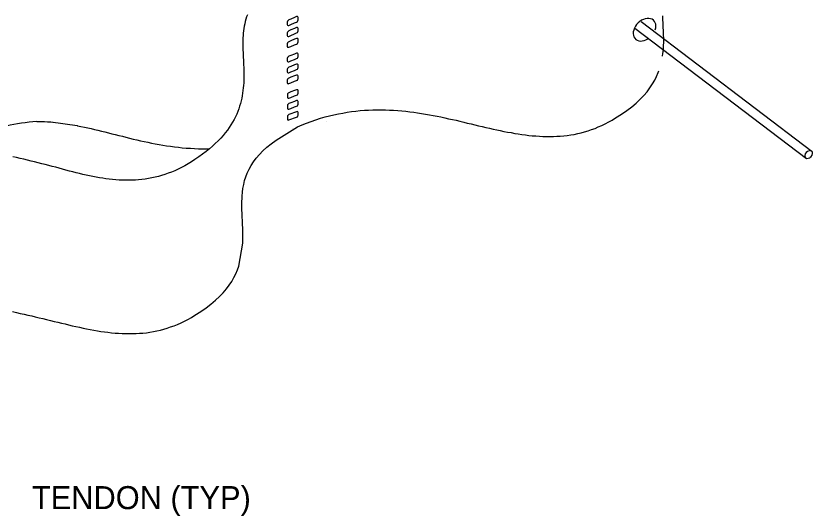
# Model space of a CAD drawing. Extents: x 638850 to 644908, y 297188 to 298900.
# Drawn here: x 639299.1 to 639402.9, y 297714.3 to 297779.5 of the extents above; entities that cross this region are included whole.
import ezdxf

# ---------------------------------------------------------------- set-up
doc = ezdxf.new("R2010")
doc.units = 0
for name, color, linetype in [('1', 7, 'Continuous'), ('16', 7, 'Continuous'), ('2', 7, 'Continuous')]:
    doc.layers.add(name, color=color, linetype=linetype)

msp = doc.modelspace()

# ---------------------------------------------------------------- linework, layer by layer
at = {"layer": '1'}
for p, q in [((639379.74, 297777.89), (639402.11, 297760.88)), ((639380.55, 297778.76), (639402.82, 297761.82))]:
    msp.add_line(p, q, dxfattribs=at)
msp.add_arc((639304.02, 297736.88), 28.92, 94.4334, 102.4037, dxfattribs=at)
for centre, major_axis, start_param in [((639380.98, 297777.69), (-1.2, -1.2), 2.18443), ((639402.37, 297761.42), (-0.416, -0.414), 1.264481)]:
    msp.add_ellipse(centre, major_axis=major_axis, ratio=0.717222, start_param=start_param, end_param=7.533439, dxfattribs=at)
at = {"layer": '16'}
for points in [[(639335.65, 297778.69), (639335.75, 297778.75), (639335.82, 297778.85), (639335.86, 297778.96), (639335.86, 297778.96), (639335.86, 297779.05), (639335.86, 297779.2), (639335.86, 297779.29), (639335.86, 297779.29), (639335.82, 297779.37), (639335.75, 297779.42), (639335.65, 297779.4), (639335.65, 297779.4), (639335.39, 297779.29), (639334.88, 297779.08), (639334.62, 297778.97), (639334.62, 297778.97), (639334.53, 297778.9), (639334.45, 297778.8), (639334.42, 297778.69), (639334.42, 297778.69), (639334.42, 297778.62), (639334.42, 297778.45), (639334.42, 297778.37), (639334.42, 297778.37), (639334.45, 297778.28), (639334.53, 297778.24), (639334.62, 297778.24), (639334.62, 297778.24), (639334.88, 297778.37), (639335.39, 297778.57), (639335.65, 297778.69), (639335.65, 297778.69), (639335.65, 297778.69)], [(639335.65, 297777.26), (639335.75, 297777.32), (639335.82, 297777.41), (639335.86, 297777.52), (639335.86, 297777.52), (639335.86, 297777.61), (639335.86, 297777.77), (639335.86, 297777.86), (639335.86, 297777.86), (639335.82, 297777.95), (639335.75, 297777.98), (639335.65, 297777.97), (639335.65, 297777.97), (639335.39, 297777.86), (639334.88, 297777.66), (639334.62, 297777.53), (639334.62, 297777.53), (639334.53, 297777.47), (639334.45, 297777.38), (639334.42, 297777.27), (639334.42, 297777.27), (639334.42, 297777.19), (639334.42, 297777.03), (639334.42, 297776.95), (639334.42, 297776.95), (639334.45, 297776.86), (639334.53, 297776.81), (639334.62, 297776.82), (639334.62, 297776.82), (639334.88, 297776.95), (639335.39, 297777.15), (639335.65, 297777.26), (639335.65, 297777.26), (639335.65, 297777.26)], [(639335.65, 297775.82), (639335.75, 297775.9), (639335.82, 297775.99), (639335.86, 297776.1), (639335.86, 297776.1), (639335.86, 297776.18), (639335.86, 297776.35), (639335.86, 297776.42), (639335.86, 297776.42), (639335.82, 297776.52), (639335.75, 297776.55), (639335.65, 297776.55), (639335.65, 297776.55), (639335.39, 297776.44), (639334.88, 297776.22), (639334.62, 297776.11), (639334.62, 297776.11), (639334.53, 297776.05), (639334.45, 297775.96), (639334.42, 297775.85), (639334.42, 297775.85), (639334.42, 297775.76), (639334.42, 297775.6), (639334.42, 297775.53), (639334.42, 297775.53), (639334.45, 297775.43), (639334.53, 297775.39), (639334.62, 297775.4), (639334.62, 297775.4), (639334.88, 297775.51), (639335.39, 297775.71), (639335.65, 297775.82), (639335.65, 297775.82), (639335.65, 297775.82)], [(639335.65, 297773.92), (639335.75, 297773.98), (639335.82, 297774.08), (639335.86, 297774.18), (639335.86, 297774.18), (639335.86, 297774.26), (639335.86, 297774.43), (639335.86, 297774.51), (639335.86, 297774.51), (639335.82, 297774.6), (639335.75, 297774.65), (639335.65, 297774.63), (639335.65, 297774.63), (639335.39, 297774.52), (639334.88, 297774.32), (639334.62, 297774.22), (639334.62, 297774.22), (639334.53, 297774.15), (639334.45, 297774.06), (639334.42, 297773.95), (639334.42, 297773.95), (639334.42, 297773.88), (639334.42, 297773.71), (639334.42, 297773.63), (639334.42, 297773.63), (639334.45, 297773.54), (639334.53, 297773.49), (639334.62, 297773.5), (639334.62, 297773.5), (639334.88, 297773.61), (639335.39, 297773.81), (639335.65, 297773.92), (639335.65, 297773.92), (639335.65, 297773.92)], [(639335.65, 297772.49), (639335.75, 297772.55), (639335.82, 297772.64), (639335.86, 297772.75), (639335.86, 297772.75), (639335.86, 297772.84), (639335.86, 297773), (639335.86, 297773.09), (639335.86, 297773.09), (639335.82, 297773.17), (639335.75, 297773.21), (639335.65, 297773.2), (639335.65, 297773.2), (639335.39, 297773.1), (639334.88, 297772.9), (639334.62, 297772.79), (639334.62, 297772.79), (639334.53, 297772.73), (639334.45, 297772.64), (639334.42, 297772.53), (639334.42, 297772.53), (639334.42, 297772.45), (639334.42, 297772.29), (639334.42, 297772.21), (639334.42, 297772.21), (639334.45, 297772.12), (639334.53, 297772.07), (639334.62, 297772.08), (639334.62, 297772.08), (639334.88, 297772.19), (639335.39, 297772.38), (639335.65, 297772.49), (639335.65, 297772.49), (639335.65, 297772.49)], [(639335.65, 297771.05), (639335.75, 297771.11), (639335.82, 297771.22), (639335.86, 297771.31), (639335.86, 297771.31), (639335.86, 297771.41), (639335.86, 297771.56), (639335.86, 297771.65), (639335.86, 297771.65), (639335.82, 297771.74), (639335.75, 297771.78), (639335.65, 297771.78), (639335.65, 297771.78), (639335.39, 297771.67), (639334.88, 297771.48), (639334.62, 297771.37), (639334.62, 297771.37), (639334.53, 297771.31), (639334.45, 297771.22), (639334.42, 297771.11), (639334.42, 297771.11), (639334.42, 297771.02), (639334.42, 297770.86), (639334.42, 297770.79), (639334.42, 297770.79), (639334.45, 297770.69), (639334.53, 297770.65), (639334.62, 297770.66), (639334.62, 297770.66), (639334.88, 297770.77), (639335.39, 297770.96), (639335.65, 297771.05), (639335.65, 297771.05), (639335.65, 297771.05)], [(639335.65, 297769.15), (639335.76, 297769.21), (639335.82, 297769.3), (639335.86, 297769.41), (639335.86, 297769.41), (639335.86, 297769.5), (639335.86, 297769.66), (639335.86, 297769.75), (639335.86, 297769.75), (639335.82, 297769.83), (639335.76, 297769.87), (639335.65, 297769.86), (639335.65, 297769.86), (639335.39, 297769.77), (639334.88, 297769.58), (639334.62, 297769.47), (639334.62, 297769.47), (639334.53, 297769.41), (639334.45, 297769.32), (639334.44, 297769.21), (639334.44, 297769.21), (639334.44, 297769.13), (639334.44, 297768.96), (639334.44, 297768.89), (639334.44, 297768.89), (639334.45, 297768.79), (639334.53, 297768.76), (639334.62, 297768.76), (639334.62, 297768.76), (639334.88, 297768.87), (639335.39, 297769.06), (639335.65, 297769.15), (639335.65, 297769.15), (639335.65, 297769.15)], [(639335.65, 297767.71), (639335.76, 297767.77), (639335.82, 297767.87), (639335.86, 297767.98), (639335.86, 297767.98), (639335.86, 297768.07), (639335.86, 297768.22), (639335.86, 297768.32), (639335.86, 297768.32), (639335.82, 297768.39), (639335.76, 297768.44), (639335.65, 297768.44), (639335.65, 297768.44), (639335.39, 297768.33), (639334.88, 297768.15), (639334.62, 297768.05), (639334.62, 297768.05), (639334.53, 297767.99), (639334.45, 297767.9), (639334.44, 297767.79), (639334.44, 297767.79), (639334.44, 297767.71), (639334.44, 297767.54), (639334.44, 297767.47), (639334.44, 297767.47), (639334.45, 297767.37), (639334.53, 297767.33), (639334.62, 297767.34), (639334.62, 297767.34), (639334.88, 297767.43), (639335.39, 297767.62), (639335.65, 297767.71), (639335.65, 297767.71), (639335.65, 297767.71)], [(639335.65, 297766.29), (639335.76, 297766.35), (639335.82, 297766.45), (639335.86, 297766.54), (639335.86, 297766.54), (639335.86, 297766.63), (639335.86, 297766.8), (639335.86, 297766.88), (639335.86, 297766.88), (639335.82, 297766.97), (639335.76, 297767.02), (639335.65, 297767), (639335.65, 297767), (639335.39, 297766.91), (639334.88, 297766.72), (639334.62, 297766.63), (639334.62, 297766.63), (639334.53, 297766.57), (639334.45, 297766.48), (639334.44, 297766.37), (639334.44, 297766.37), (639334.44, 297766.29), (639334.44, 297766.12), (639334.44, 297766.05), (639334.44, 297766.05), (639334.45, 297765.95), (639334.53, 297765.91), (639334.62, 297765.92), (639334.62, 297765.92), (639334.88, 297766.01), (639335.39, 297766.2), (639335.65, 297766.29), (639335.65, 297766.29), (639335.65, 297766.29)]]:
    msp.add_lwpolyline(points, dxfattribs=at)
at = {"layer": '2'}
for p, q in [((639339.35, 297766.31), (639339.94, 297766.46)), ((639339.94, 297766.46), (639340.5, 297766.6)), ((639340.5, 297766.6), (639341.09, 297766.72)), ((639341.09, 297766.72), (639341.67, 297766.83)), ((639341.67, 297766.83), (639342.23, 297766.93)), ((639342.23, 297766.93), (639342.79, 297767.02)), ((639342.79, 297767.02), (639343.36, 297767.08)), ((639343.36, 297767.08), (639343.92, 297767.14)), ((639343.92, 297767.14), (639344.48, 297767.19)), ((639344.48, 297767.19), (639345.03, 297767.22)), ((639345.03, 297767.22), (639345.59, 297767.24)), ((639345.59, 297767.24), (639346.13, 297767.25)), ((639346.13, 297767.25), (639346.67, 297767.25)), ((639346.67, 297767.25), (639347.21, 297767.24)), ((639347.21, 297767.24), (639347.75, 297767.22)), ((639347.75, 297767.22), (639348.27, 297767.19)), ((639348.27, 297767.19), (639348.82, 297767.16)), ((639348.82, 297767.16), (639349.34, 297767.11)), ((639349.34, 297767.11), (639349.86, 297767.05)), ((639303.63, 297765.66), (639307.04, 297765.19)), ((639336.35, 297765.29), (639336.95, 297765.52)), ((639336.95, 297765.52), (639337.56, 297765.74)), ((639337.56, 297765.74), (639338.16, 297765.95)), ((639338.16, 297765.95), (639338.76, 297766.14)), ((639338.76, 297766.14), (639339.35, 297766.31)), ((639339.59, 297765.71), (639339.59, 297765.71)), ((639333.67, 297763.71), (639335.75, 297765.03)), ((639335.13, 297764.75), (639335.13, 297764.75)), ((639335.75, 297765.03), (639336.35, 297765.29)), ((639332.98, 297763.27), (639333.67, 297763.71)), ((639331.26, 297761.89), (639331.77, 297762.36)), ((639331.77, 297762.36), (639332.34, 297762.82)), ((639332.34, 297762.82), (639332.98, 297763.27)), ((639330.38, 297760.94), (639330.8, 297761.41)), ((639330.8, 297761.41), (639331.26, 297761.89)), ((639329.72, 297759.99), (639330.03, 297760.46)), ((639330.03, 297760.46), (639330.38, 297760.94)), ((639329.21, 297759.01), (639329.44, 297759.5)), ((639329.44, 297759.5), (639329.72, 297759.99)), ((639328.87, 297758.02), (639329.02, 297758.51)), ((639329.02, 297758.51), (639329.21, 297759.01)), ((639328.65, 297757.01), (639328.75, 297757.52)), ((639328.75, 297757.52), (639328.87, 297758.02)), ((639328.53, 297756.01), (639328.58, 297756.5)), ((639328.58, 297756.5), (639328.65, 297757.01)), ((639328.5, 297754.99), (639328.53, 297756.01)), ((639328.5, 297754.59), (639328.5, 297754.99)), ((639328.5, 297754.99), (639328.5, 297754.99)), ((639328.51, 297754.17), (639328.5, 297754.59)), ((639328.53, 297753.77), (639328.51, 297754.17)), ((639328.56, 297753.27), (639328.53, 297753.77)), ((639328.59, 297752.8), (639328.56, 297753.27)), ((639328.61, 297752.3), (639328.59, 297752.8)), ((639328.64, 297751.82), (639328.61, 297752.3)), ((639328.65, 297751.33), (639328.64, 297751.82)), ((639328.65, 297750.84), (639328.65, 297751.33)), ((639328.12, 297746.85), (639328.64, 297749.85)), ((639328.64, 297749.85), (639328.65, 297750.34)), ((639328.65, 297750.34), (639328.65, 297750.84))]:
    msp.add_line(p, q, dxfattribs=at)
for points in [[(639329.24, 297779.64), (639329.13, 297779.35), (639329.04, 297779.05), (639328.95, 297778.74), (639328.88, 297778.45), (639328.82, 297778.14), (639328.78, 297777.84), (639328.73, 297777.54), (639328.7, 297777.23), (639328.67, 297776.92), (639328.65, 297776.61), (639328.65, 297776.29), (639328.64, 297775.98), (639328.64, 297775.67), (639328.65, 297775.34), (639328.65, 297775.03), (639328.67, 297774.71), (639328.68, 297774.39), (639328.7, 297774.06), (639328.72, 297773.74), (639328.72, 297773.41), (639328.73, 297773.09), (639328.75, 297772.76), (639328.76, 297772.43), (639328.76, 297772.1), (639328.76, 297771.78), (639328.76, 297771.44), (639328.76, 297771.11), (639328.75, 297770.78), (639328.72, 297770.43), (639328.7, 297770.09), (639328.65, 297769.77), (639328.61, 297769.43), (639328.56, 297769.09), (639328.5, 297768.75), (639328.42, 297768.41), (639328.33, 297768.05), (639328.22, 297767.72), (639328.11, 297767.38), (639327.99, 297767.04), (639327.84, 297766.7), (639327.68, 297766.34), (639327.5, 297766), (639327.31, 297765.65), (639327.09, 297765.31), (639326.86, 297764.95), (639326.62, 297764.61), (639326.35, 297764.26), (639326.06, 297763.92), (639325.75, 297763.56), (639325.41, 297763.22), (639325.05, 297762.87), (639324.69, 297762.51), (639324.28, 297762.16), (639323.85, 297761.82), (639323.39, 297761.46), (639322.91, 297761.1), (639322.4, 297760.76), (639322.4, 297760.76), (639322.4, 297760.76)], [(639383.34, 297774.25), (639383.38, 297774.59), (639383.44, 297775.08), (639383.47, 297775.58), (639383.49, 297776.07), (639383.49, 297776.56), (639383.47, 297777.06), (639383.45, 297777.54), (639383.42, 297778.03), (639383.41, 297778.52), (639383.38, 297779), (639383.35, 297779.48)], [(639349.86, 297767.05), (639350.38, 297766.99), (639350.9, 297766.93), (639351.41, 297766.85), (639351.93, 297766.77), (639352.44, 297766.7), (639352.95, 297766.6), (639353.45, 297766.51), (639353.96, 297766.4), (639354.45, 297766.31), (639354.96, 297766.2), (639355.45, 297766.09), (639355.95, 297765.98), (639356.44, 297765.88), (639356.92, 297765.75), (639357.42, 297765.64), (639357.89, 297765.52), (639358.39, 297765.41), (639358.87, 297765.29), (639359.35, 297765.18), (639359.83, 297765.07), (639360.31, 297764.95), (639360.77, 297764.84), (639361.25, 297764.74), (639361.73, 297764.64), (639362.19, 297764.53), (639362.65, 297764.44), (639363.13, 297764.35), (639363.59, 297764.27), (639364.06, 297764.18), (639364.52, 297764.12), (639364.98, 297764.04), (639365.45, 297763.97), (639365.91, 297763.91), (639366.36, 297763.87), (639366.82, 297763.84), (639367.29, 297763.81), (639367.73, 297763.78), (639368.2, 297763.78), (639368.64, 297763.76), (639369.11, 297763.78), (639369.56, 297763.79), (639370, 297763.82), (639370.47, 297763.87), (639370.92, 297763.91), (639371.36, 297763.97), (639371.81, 297764.05), (639372.27, 297764.15), (639372.72, 297764.25), (639373.17, 297764.38), (639373.62, 297764.51), (639374.07, 297764.66), (639374.53, 297764.83), (639374.96, 297765.01), (639375.41, 297765.21), (639375.86, 297765.43), (639376.32, 297765.66), (639376.77, 297765.91), (639377.22, 297766.18), (639377.22, 297766.18), (639377.97, 297766.66), (639378.67, 297767.16), (639379.32, 297767.65), (639379.89, 297768.13), (639380.41, 297768.63), (639380.89, 297769.12), (639381.31, 297769.61), (639381.68, 297770.11), (639382.02, 297770.62), (639382.31, 297771.11), (639382.56, 297771.61), (639382.78, 297772.1), (639382.86, 297772.33)], [(639301.79, 297765.72), (639301.92, 297765.72), (639302.35, 297765.72), (639302.79, 297765.71), (639303.2, 297765.69), (639303.63, 297765.66), (639303.79, 297765.65)], [(639307.04, 297765.19), (639307.11, 297765.18), (639307.54, 297765.09), (639307.99, 297765), (639308.42, 297764.89), (639308.87, 297764.8), (639309.32, 297764.69), (639309.76, 297764.58), (639310.21, 297764.47), (639310.66, 297764.36), (639311.11, 297764.24), (639311.56, 297764.13), (639312.02, 297764.01), (639312.48, 297763.9), (639312.95, 297763.79), (639313.41, 297763.67), (639313.87, 297763.56), (639314.34, 297763.44), (639314.81, 297763.33), (639315.29, 297763.22), (639315.77, 297763.11), (639316.25, 297763.02), (639316.73, 297762.91), (639317.22, 297762.82), (639317.72, 297762.73), (639318.21, 297762.65), (639318.71, 297762.57), (639319.22, 297762.5), (639319.72, 297762.43), (639320.24, 297762.37), (639320.75, 297762.31), (639321.27, 297762.26), (639321.8, 297762.23), (639322.32, 297762.2), (639322.86, 297762.18), (639323.39, 297762.17), (639323.93, 297762.17), (639324.3, 297762.17)], [(639322.4, 297760.76), (639321.95, 297760.47), (639321.52, 297760.22), (639321.09, 297759.96), (639320.64, 297759.73), (639320.21, 297759.52), (639319.77, 297759.31), (639319.34, 297759.14), (639318.91, 297758.98), (639318.48, 297758.82), (639318.04, 297758.68), (639317.63, 297758.56), (639317.19, 297758.45), (639316.76, 297758.36), (639316.35, 297758.28), (639315.91, 297758.22), (639315.49, 297758.16), (639315.06, 297758.13), (639314.65, 297758.09), (639314.21, 297758.08), (639313.8, 297758.06), (639313.36, 297758.06), (639312.93, 297758.08), (639312.52, 297758.09), (639312.08, 297758.13), (639311.67, 297758.17), (639311.23, 297758.22), (639310.8, 297758.26), (639310.38, 297758.32), (639309.95, 297758.4), (639309.52, 297758.48), (639309.08, 297758.56), (639308.65, 297758.65), (639308.22, 297758.74), (639307.79, 297758.83), (639307.36, 297758.94), (639306.91, 297759.05), (639306.48, 297759.16), (639306.03, 297759.27), (639305.58, 297759.37), (639305.15, 297759.5), (639304.7, 297759.62), (639304.25, 297759.75), (639303.79, 297759.86), (639303.34, 297759.98), (639302.89, 297760.1), (639302.43, 297760.22), (639301.97, 297760.33), (639301.5, 297760.46), (639301.04, 297760.56), (639300.56, 297760.69), (639300.1, 297760.8), (639299.62, 297760.91), (639299.14, 297761.01), (639298.66, 297761.12)], [(639318.79, 297738.79), (639319.23, 297738.94), (639319.68, 297739.11), (639320.14, 297739.28), (639320.59, 297739.48), (639321.04, 297739.7), (639321.49, 297739.93), (639321.95, 297740.18), (639322.4, 297740.46), (639322.4, 297740.46), (639323.15, 297740.95), (639323.85, 297741.43), (639324.48, 297741.93), (639325.07, 297742.42), (639325.59, 297742.91), (639326.06, 297743.41), (639326.49, 297743.9), (639326.86, 297744.4), (639327.2, 297744.89), (639327.48, 297745.38), (639327.74, 297745.88), (639327.94, 297746.37), (639328.12, 297746.85)], [(639298.62, 297740.94), (639299.12, 297740.83), (639299.62, 297740.72), (639300.13, 297740.61), (639300.62, 297740.5), (639301.12, 297740.38), (639301.59, 297740.27), (639302.09, 297740.15), (639302.59, 297740.03), (639303.06, 297739.92), (639303.56, 297739.79), (639304.04, 297739.67), (639304.51, 297739.56), (639304.99, 297739.44), (639305.47, 297739.33), (639305.93, 297739.21), (639306.41, 297739.1), (639306.88, 297738.99), (639307.36, 297738.9), (639307.82, 297738.79), (639308.28, 297738.7), (639308.76, 297738.6), (639309.23, 297738.53), (639309.69, 297738.45), (639310.15, 297738.37), (639310.62, 297738.31), (639311.06, 297738.25), (639311.53, 297738.2), (639311.99, 297738.15), (639312.44, 297738.13), (639312.9, 297738.09), (639313.35, 297738.08), (639313.81, 297738.08), (639314.26, 297738.08), (639314.72, 297738.09), (639315.17, 297738.13), (639315.62, 297738.15), (639316.08, 297738.2), (639316.53, 297738.26), (639316.98, 297738.34), (639317.43, 297738.43), (639317.89, 297738.54), (639318.34, 297738.67), (639318.79, 297738.79)]]:
    msp.add_lwpolyline(points, dxfattribs=at)

# ---------------------------------------------------------------- texts
at = {"layer": '1'}
msp.add_text('TENDON (TYP)', height=3, dxfattribs=at).set_placement((639301.15, 297715.2))

doc.saveas('drawing.dxf')
